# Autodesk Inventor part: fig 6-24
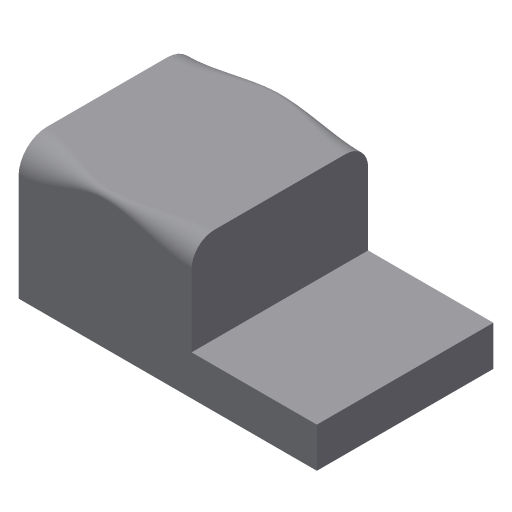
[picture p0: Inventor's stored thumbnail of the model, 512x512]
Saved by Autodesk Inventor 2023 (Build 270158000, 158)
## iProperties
Created: 2004-05
Part Number: fig 6-24
Document SubType Name: Modeling
Designer: CADCIM Technologies
Manufacturer: Standard
Standards Organization: Custom
Density: 1 g/cm^3
Material: Generic
Appearance: Default
Author: CADCIM Technologies
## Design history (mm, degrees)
node "Sketch1"
sketch "Sketch2"
  geometry: L1 (0.098, 47.711)-(0.098, 0.049); L2 (0.098, 0.049)-(-105.483, 0.049); L3 (-105.483, 0.049)-(-105.483, 14.192); L4 (-105.483, 14.192)-(-61.139, 14.192); L5 (-61.139, 14.192)-(-61.139, 47.711); L6 (-61.139, 47.711)-(0.098, 47.711)
  constraints: 12 end point, 3 parallel, 2 perpendicular, 1 vertical
extrude "Extrusion1" new body sketch "Sketch2" stored distance "d0" = 62.5; taper "d1" = 0 deg
fillet "Fillet9" dims "d61" = 10, "d62" = 8, "d63" = 2, "d64" = 5
fillet "Fillet10" dims "d65" = 8, "d66" = 10, "d67" = 2, "d68" = 5
body "Solid1"
